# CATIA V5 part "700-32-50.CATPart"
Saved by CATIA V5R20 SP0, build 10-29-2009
Part number: 700-32-50
Revision: ANY
Definition: UNKNOWN
Nomenclature: 700-32-50
Source: Unknown
Bounding box of the stored display mesh (mm): x -16 to 16, y 0 to 50, z -16 to 16
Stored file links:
  C:\Users\Utente\Desktop\IO LAVORO\3D X SITO CF\X SITO\700\700-32-50.CATPart
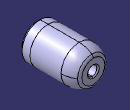
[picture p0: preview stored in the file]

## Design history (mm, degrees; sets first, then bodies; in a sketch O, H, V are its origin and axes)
Body1 "Rivoluzione1" (main body)
  Solid1: solid without history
